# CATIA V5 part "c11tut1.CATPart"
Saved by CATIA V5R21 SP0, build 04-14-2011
Part number: c11tut1
Bounding box of the stored display mesh (mm): x -74.368 to 0, y -50 to 50, z -100 to 0
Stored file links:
  D:\CATIA V5R21 E-RESOURCES\CATIA-V5R21\catia-v5r21-prt\c11-catia-v5r21-prt\c11-catia-v5r21-tut01.CATPart
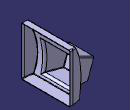
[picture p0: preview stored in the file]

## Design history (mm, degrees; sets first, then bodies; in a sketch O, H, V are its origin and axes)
Body1 (main body)
  Sketch1 on zx-plane, origin (0, 0, 0), H (-1, 0, 0), V (0, 0, 1)
    line L1 (0, 0) -> (12, 0)
    line L2 (0, -100) -> (22, -100)
    point P2 (0, -100)
    arc A1 centre (-96.8872, -61.3887) radius 125 from (12, 0) to (22, -100) cw
    length L1 = 12
    length L2 = 22
    radius A1 = 125
    distance L2 L1 = 100
    horizontal: L1 H, L2 H
    coincidence: P2 V
  Extrude1: Element1 Sketch1, Lim1 50, Lim2 50, Direction zx-plane
  Sketch2 on zx-plane, origin (0, 0, 0), H (-1, 0, 0), V (0, 0, 1)
    line L1 (20, -40) -> (74.9495, -60)
    point P1 (20, -40)
    point P2 (74.9495, -60)
    reference projected line E1 (22, -100) -> (0, -100) from edge of Extrude1
    angle L1 H = 20
    distance P1 V = 20
    distance E1 P1 = 60
    distance H P2 = 60
  Plane1: type Normal, Curve Sketch2, RefPoint Sketch2.P2
  Sketch3 on Plane1, origin (-85.4657, 0, -31.107), H (0, -1, 0), V (-0.342, 0, 0.9397)
    line L1 (-25, -30.7473) -> (25, -30.7473)
    line L2 (25, -30.7473) -> (25, -70.7473)
    line L3 (25, -70.7473) -> (-25, -70.7473)
    line L4 (-25, -70.7473) -> (-25, -30.7473)
    reference projected point E1 (0, -30.7473) from Sketch2.P2
    reference projected point E2 (0, -30.7473) from Sketch2.P2
    length L2 = 40
    length L3 = 50
    distance L4 E2 = 25
    horizontal: L1 H, L3 H
    vertical: L2 V, L4 V
    coincidence: E1 L1
  Plane2: type Normal, Curve Sketch2, RefPoint Sketch2.P1
  Sketch4 on Plane2, origin (-30.5162, 0, -11.107), H (0, -1, 0), V (-0.342, 0, 0.9397)
    line L1 (-32.5, -21.2473) -> (32.5, -21.2473)
    line L2 (32.5, -21.2473) -> (32.5, -81.2473)
    line L3 (32.5, -81.2473) -> (-32.5, -81.2473)
    line L4 (-32.5, -81.2473) -> (-32.5, -21.2473)
    reference projected line E1 (25, -30.7473) -> (-25, -30.7473) from Sketch3.L1
    distance E1 L1 = 9.5
    length L2 = 60
    distance L4 L2 = 65
    distance V L2 = 32.5
    horizontal: L1 H, L3 H
    vertical: L2 V, L4 V
  Loft1: Sections (Sketch4; Sketch3)
  Sketch5 on face of Extrude1 from Sketch1.L1, origin (0, 0, 0), H (1, 0, 0), V (0, -1, 0)
    line L1 (-5, -50) -> (0, -50)
    point P2 (0, -50)
    arc A1 centre (-5, 0) radius 50 from (-29.6886, -43.4796) to (-5, -50) ccw
    reference projected line E1 (0, -50) -> (0, 50) from edge of Extrude1
    reference projected line E2 (-22, -50) -> (0, -50) from edge of Extrude1
    length L1 = 5
    radius A1 = 50
    horizontal: L1 H
    tangency: A1 L1
    coincidence: P2 E1, L1 E2
  Extrude2: Element1 Sketch5, Lim1 100, Lim2 0
  Symmetry1: ToTransfor Extrude2, Reference zx-plane
  Trim1: Trimmed (Extrude2; Extrude1)
  Trim2: Trimmed (Symmetry1; Trim1)
  Trim3: Trimmed (Trim2; Loft1)
  CloseSurface1: CloseElement Trim3
  Sketch6 on face of CloseSurface1, origin (-85.4657, 0, -31.107), H (0, -1, 0), V (-0.342, 0, 0.9397)
    line L1 (-20, -55.7473) -> (0, -55.7473)
    line L2 (0, -55.7473) -> (0, -65.7473)
    line L3 (0, -65.7473) -> (-20, -65.7473)
    line L4 (-20, -65.7473) -> (-20, -55.7473)
    reference projected line E1 (-25, -70.7473) -> (25, -70.7473) from edge [face of CloseSurface1 | face of CloseSurface1]
    reference projected line E2 (-25, -30.7473) -> (-25, -70.7473) from edge [face of CloseSurface1 | face of CloseSurface1]
    length L1 = 20
    length L4 = 10
    distance E1 L3 = 5
    distance L4 E2 = 5
    horizontal: L1 H, L3 H
    vertical: L2 V, L4 V
  Pocket1: profile Sketch6, direction (0.9397, 0, 0.342), length 5
  Fillet1: radius 1, on end face of Pocket1; edge [face of Pocket1 from Sketch6.L1 | face of Pocket1 from Sketch6.L2]; edge [face of Pocket1 from Sketch6.L4 | face of Pocket1 from Sketch6.L1]; edge [face of Pocket1 from Sketch6.L2 | face of Pocket1 from Sketch6.L3]; edge [face of Pocket1 from Sketch6.L3 | face of Pocket1 from Sketch6.L4]
  Fillet2: radius 3.5, on edge [face of CloseSurface1 | face of CloseSurface1] (x4)
  Fillet3: radius 2, on face of CloseSurface1; edge [face of CloseSurface1 | face of CloseSurface1] (x4)
  Shell1: ExtOffset 0, Face face of CloseSurface1, IntOffset 1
